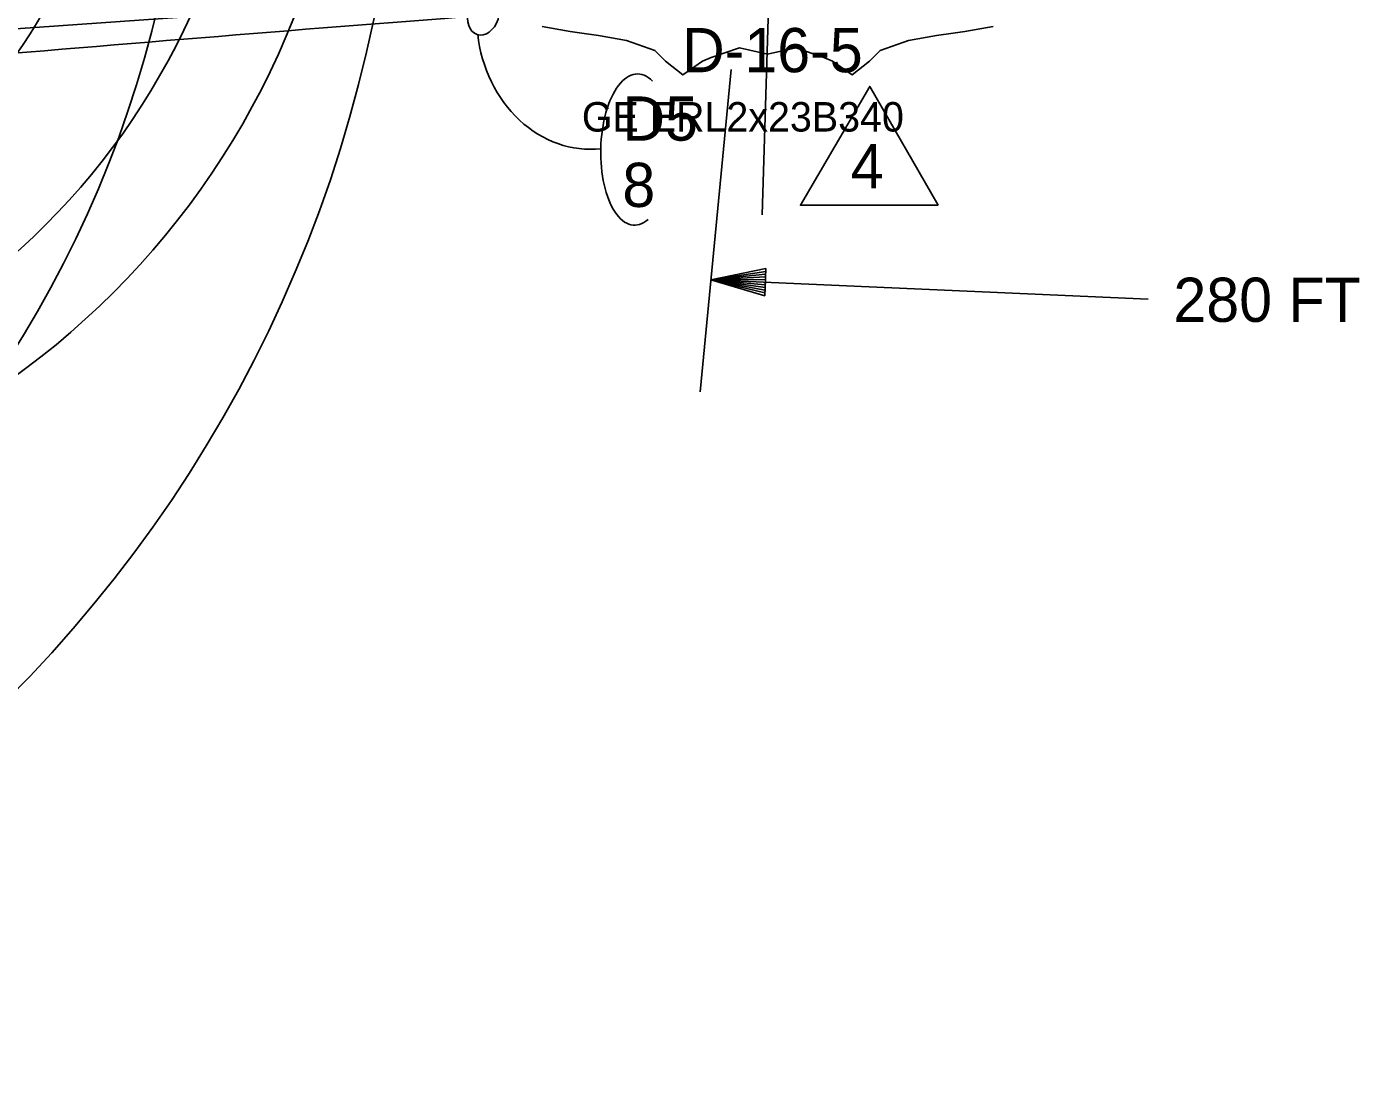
# Model space of a CAD drawing. Extents: x 1638506 to 1658005, y 834807 to 846788.
# Drawn here: x 1642259.2 to 1642621, y 841870 to 842159.5 of the extents above; entities that cross this region are included whole.
import ezdxf

# ---------------------------------------------------------------- set-up
doc = ezdxf.new("R2010")
doc.units = 0
for name, color, linetype in [('Default', 7, 'Continuous'), ('Old_Level_1', 7, 'Continuous'), ('Old_Level_2', 7, 'Continuous'), ('Scratch_Level_0', 7, 'Continuous')]:
    doc.layers.add(name, color=color, linetype=linetype)

msp = doc.modelspace()

# ---------------------------------------------------------------- linework, layer by layer
at = {"layer": 'Default'}
for p, q in [((1642442, 842060.33), (1642450.39, 842147.87)), ((1642444.92, 842090.75), (1642563.67, 842085.5))]:
    msp.add_line(p, q, dxfattribs=at)
msp.add_lwpolyline([(1642506.63, 842110.98), (1642469.24, 842110.98), (1642488.07, 842143.24)], close=True, dxfattribs=at)
msp.add_lwpolyline([(1642459.7, 842090.1), (1642459.67, 842089.36), (1642444.92, 842090.75), (1642459.64, 842088.67), (1642459.6, 842087.93), (1642444.92, 842090.75), (1642459.57, 842087.19), (1642459.54, 842086.45), (1642444.92, 842090.75), (1642459.81, 842093.8), (1642459.83, 842093.05), (1642444.92, 842090.75), (1642459.75, 842092.32), (1642459.76, 842091.58), (1642444.92, 842090.75), (1642459.73, 842090.84), (1642459.54, 842086.45), (1642459.81, 842093.8), (1642444.92, 842090.75), (1642459.54, 842086.45)], dxfattribs=at)
msp.add_arc((1643863.61, 823017.34), 19202.35, 94.226402, 95.13232, dxfattribs=at)
msp.add_ellipse((1642383.2, 842162.72), major_axis=(1.72, 5.4), ratio=0.730797, dxfattribs=at)
for centre, major_axis, ratio, start_param, end_param in [((1642411.26, 842160.69), (-3.78, 34.34), 0.862742, 1.570796, 3.141593), ((1642424.61, 842126.12), (-0.49, -20.52), 0.466223, 2.710831, 4.712389), ((1642424.61, 842126.12), (-0.49, -20.52), 0.466223, 4.712389, 6.681485)]:
    msp.add_ellipse(centre, major_axis=major_axis, ratio=ratio, start_param=start_param, end_param=end_param, dxfattribs=at)
at = {"layer": 'Old_Level_1'}
msp.add_lwpolyline([(1642399.11, 842159.52), (1642406.76, 842158.12), (1642409.89, 842157.72), (1642414.41, 842157.09), (1642422.06, 842155.7), (1642429.71, 842153.04), (1642432.6, 842150.07), (1642437.36, 842146.35), (1642442.69, 842150.07), (1642445.01, 842151.13), (1642452.66, 842153.73), (1642460.31, 842152.04), (1642467.96, 842153.73), (1642475.61, 842151.13), (1642477.94, 842150.07), (1642483.26, 842146.35), (1642488.02, 842150.07), (1642490.91, 842153.04), (1642498.56, 842155.7), (1642506.21, 842157.09), (1642510.73, 842157.72), (1642513.86, 842158.12), (1642521.51, 842159.52)], dxfattribs=at)
for radius in [365, 307]:
    msp.add_circle((1641995.81, 842234.97), radius, dxfattribs=at)
at = {"layer": 'Old_Level_2'}
for p, q in [((1642458.82, 842108.44), (1642469.85, 842461.62)), ((1642519.11, 842177.39), (1642217.73, 842156.22))]:
    msp.add_line(p, q, dxfattribs=at)
at = {"layer": 'Scratch_Level_0'}
for radius in [219, 193, 157]:
    msp.add_circle((1642127.87, 842242.15), radius, dxfattribs=at)

# ---------------------------------------------------------------- texts
at = {"layer": 'Default'}
for s, p in [('D-16-5', (1642437.09, 842147.1)), ('D5', (1642420.9, 842128.53)), ('4', (1642482.89, 842115.58)), ('8', (1642420.9, 842110.53)), ('280 FT', (1642570.48, 842079.35))]:
    msp.add_text(s, height=12, dxfattribs=at).set_placement(p)
at = {"layer": 'Old_Level_1'}
msp.add_text('GE ERL2x23B340', height=8, dxfattribs=at).set_placement((1642409.9, 842131))

doc.saveas('drawing.dxf')
